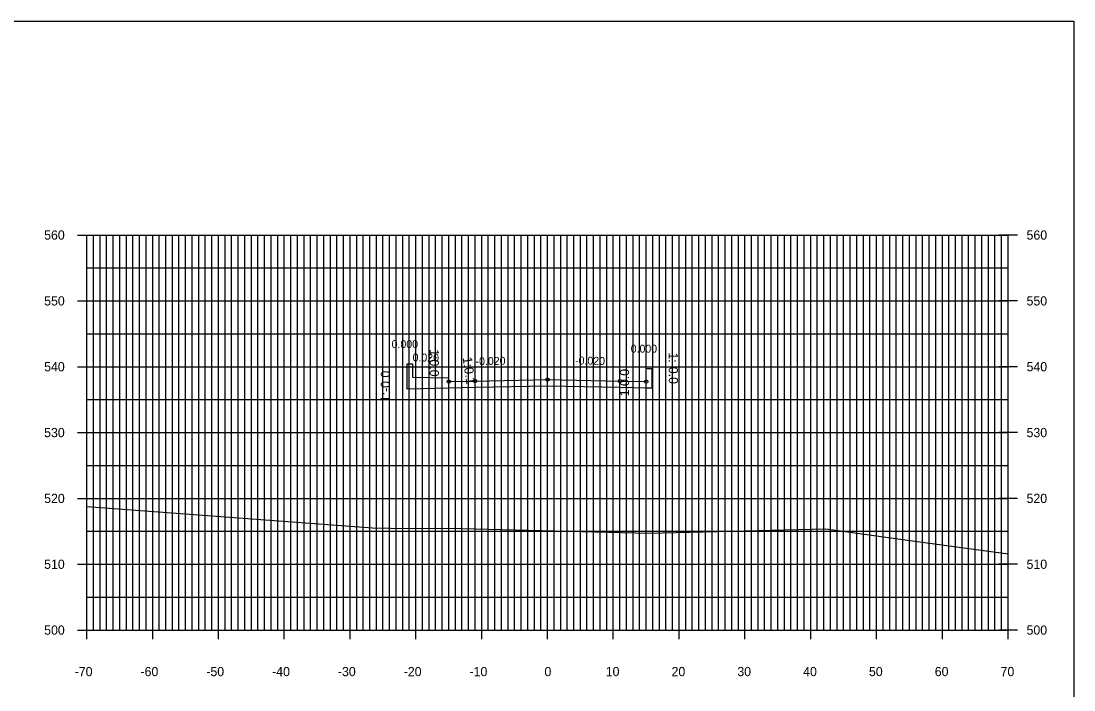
# Model space of a CAD drawing. Extents: x 1509063 to 1512863, y 401160 to 402918.
# Drawn here: x 1511262.7 to 1511422.7, y 402360.5 to 402462.1 of the extents above; entities that cross this region are included whole.
import ezdxf

# ---------------------------------------------------------------- set-up
doc = ezdxf.new("R2010")
doc.units = 0
for name, color, linetype in [('NBL1', 7, 'Continuous'), ('PET_P', 7, 'Continuous'), ('PRC', 7, 'Continuous'), ('PSP_P', 7, 'Continuous'), ('XAX_P', 7, 'Continuous'), ('XAXTIC_P', 7, 'Continuous'), ('XAXTXT_P_T', 7, 'Continuous'), ('XGL_P', 7, 'Continuous'), ('XSL1_P', 7, 'Continuous'), ('XSL1_P_T', 7, 'Continuous'), ('XSL3_P', 7, 'Continuous'), ('XSLOG', 7, 'Continuous')]:
    doc.layers.add(name, color=color, linetype=linetype)

msp = doc.modelspace()

# ---------------------------------------------------------------- linework, layer by layer
at = {"layer": 'NBL1'}
msp.add_lwpolyline([(1511422.73, 402252.08), (1511102.73, 402252.08), (1511102.73, 402462.08), (1511422.73, 402462.08)], close=True, dxfattribs=at)
at = {"layer": 'PET_P'}
for centre in [(1511331.73, 402407.4), (1511353.73, 402407.4)]:
    msp.add_circle(centre, 0.25, dxfattribs=at)
at = {"layer": 'PRC'}
msp.add_circle((1511342.73, 402407.62), 0.25, dxfattribs=at)
at = {"layer": 'PSP_P'}
for centre in [(1511327.73, 402407.32), (1511357.73, 402407.32)]:
    msp.add_circle(centre, 0.25, dxfattribs=at)
at = {"layer": 'XAX_P'}
for p, q in [((1511272.73, 402369.58), (1511272.73, 402429.58)), ((1511342.73, 402369.58), (1511342.73, 402429.58)), ((1511412.73, 402369.58), (1511412.73, 402429.58)), ((1511272.73, 402369.58), (1511412.73, 402369.58))]:
    msp.add_line(p, q, dxfattribs=at)
at = {"layer": 'XAXTIC_P'}
for p, q in [((1511271.33, 402429.58), (1511274.13, 402429.58)), ((1511341.33, 402429.58), (1511344.13, 402429.58)), ((1511414.13, 402429.58), (1511411.33, 402429.58)), ((1511271.33, 402419.58), (1511274.13, 402419.58)), ((1511341.33, 402419.58), (1511344.13, 402419.58)), ((1511414.13, 402419.58), (1511411.33, 402419.58)), ((1511271.33, 402409.58), (1511274.13, 402409.58)), ((1511341.33, 402409.58), (1511344.13, 402409.58)), ((1511414.13, 402409.58), (1511411.33, 402409.58)), ((1511271.33, 402399.58), (1511274.13, 402399.58)), ((1511341.33, 402399.58), (1511344.13, 402399.58)), ((1511414.13, 402399.58), (1511411.33, 402399.58)), ((1511271.33, 402389.58), (1511274.13, 402389.58)), ((1511341.33, 402389.58), (1511344.13, 402389.58)), ((1511414.13, 402389.58), (1511411.33, 402389.58)), ((1511271.33, 402379.58), (1511274.13, 402379.58)), ((1511341.33, 402379.58), (1511344.13, 402379.58)), ((1511414.13, 402379.58), (1511411.33, 402379.58)), ((1511272.73, 402368.18), (1511272.73, 402370.98)), ((1511282.73, 402368.18), (1511282.73, 402370.98)), ((1511292.73, 402368.18), (1511292.73, 402370.98)), ((1511302.73, 402368.18), (1511302.73, 402370.98)), ((1511312.73, 402368.18), (1511312.73, 402370.98)), ((1511322.73, 402368.18), (1511322.73, 402370.98)), ((1511332.73, 402368.18), (1511332.73, 402370.98)), ((1511342.73, 402368.18), (1511342.73, 402370.98)), ((1511352.73, 402368.18), (1511352.73, 402370.98)), ((1511362.73, 402368.18), (1511362.73, 402370.98)), ((1511372.73, 402368.18), (1511372.73, 402370.98)), ((1511382.73, 402368.18), (1511382.73, 402370.98)), ((1511392.73, 402368.18), (1511392.73, 402370.98)), ((1511402.73, 402368.18), (1511402.73, 402370.98)), ((1511412.73, 402368.18), (1511412.73, 402370.98)), ((1511271.33, 402369.58), (1511274.13, 402369.58)), ((1511341.33, 402369.58), (1511344.13, 402369.58)), ((1511414.13, 402369.58), (1511411.33, 402369.58))]:
    msp.add_line(p, q, dxfattribs=at)
at = {"layer": 'XGL_P'}
for p, q in [((1511272.73, 402429.58), (1511412.73, 402429.58)), ((1511272.73, 402369.58), (1511272.73, 402429.58)), ((1511273.73, 402369.58), (1511273.73, 402429.58)), ((1511274.73, 402369.58), (1511274.73, 402429.58)), ((1511275.73, 402369.58), (1511275.73, 402429.58)), ((1511276.73, 402369.58), (1511276.73, 402429.58)), ((1511277.73, 402369.58), (1511277.73, 402429.58)), ((1511278.73, 402369.58), (1511278.73, 402429.58)), ((1511279.73, 402369.58), (1511279.73, 402429.58)), ((1511280.73, 402369.58), (1511280.73, 402429.58)), ((1511281.73, 402369.58), (1511281.73, 402429.58)), ((1511282.73, 402369.58), (1511282.73, 402429.58)), ((1511283.73, 402369.58), (1511283.73, 402429.58)), ((1511284.73, 402369.58), (1511284.73, 402429.58)), ((1511285.73, 402369.58), (1511285.73, 402429.58)), ((1511286.73, 402369.58), (1511286.73, 402429.58)), ((1511287.73, 402369.58), (1511287.73, 402429.58)), ((1511288.73, 402369.58), (1511288.73, 402429.58)), ((1511289.73, 402369.58), (1511289.73, 402429.58)), ((1511290.73, 402369.58), (1511290.73, 402429.58)), ((1511291.73, 402369.58), (1511291.73, 402429.58)), ((1511292.73, 402369.58), (1511292.73, 402429.58)), ((1511293.73, 402369.58), (1511293.73, 402429.58)), ((1511294.73, 402369.58), (1511294.73, 402429.58)), ((1511295.73, 402369.58), (1511295.73, 402429.58)), ((1511296.73, 402369.58), (1511296.73, 402429.58)), ((1511297.73, 402369.58), (1511297.73, 402429.58)), ((1511298.73, 402369.58), (1511298.73, 402429.58)), ((1511299.73, 402369.58), (1511299.73, 402429.58)), ((1511300.73, 402369.58), (1511300.73, 402429.58)), ((1511301.73, 402369.58), (1511301.73, 402429.58)), ((1511302.73, 402369.58), (1511302.73, 402429.58)), ((1511303.73, 402369.58), (1511303.73, 402429.58)), ((1511304.73, 402369.58), (1511304.73, 402429.58)), ((1511305.73, 402369.58), (1511305.73, 402429.58)), ((1511306.73, 402369.58), (1511306.73, 402429.58)), ((1511307.73, 402369.58), (1511307.73, 402429.58)), ((1511308.73, 402369.58), (1511308.73, 402429.58)), ((1511309.73, 402369.58), (1511309.73, 402429.58)), ((1511310.73, 402369.58), (1511310.73, 402429.58)), ((1511311.73, 402369.58), (1511311.73, 402429.58)), ((1511312.73, 402369.58), (1511312.73, 402429.58)), ((1511313.73, 402369.58), (1511313.73, 402429.58)), ((1511314.73, 402369.58), (1511314.73, 402429.58)), ((1511315.73, 402369.58), (1511315.73, 402429.58)), ((1511316.73, 402369.58), (1511316.73, 402429.58)), ((1511317.73, 402369.58), (1511317.73, 402429.58)), ((1511318.73, 402369.58), (1511318.73, 402429.58)), ((1511319.73, 402369.58), (1511319.73, 402429.58)), ((1511320.73, 402369.58), (1511320.73, 402429.58)), ((1511321.73, 402369.58), (1511321.73, 402429.58)), ((1511322.73, 402369.58), (1511322.73, 402429.58)), ((1511323.73, 402369.58), (1511323.73, 402429.58)), ((1511324.73, 402369.58), (1511324.73, 402429.58)), ((1511325.73, 402369.58), (1511325.73, 402429.58)), ((1511326.73, 402369.58), (1511326.73, 402429.58)), ((1511327.73, 402369.58), (1511327.73, 402429.58)), ((1511328.73, 402369.58), (1511328.73, 402429.58)), ((1511329.73, 402369.58), (1511329.73, 402429.58)), ((1511330.73, 402369.58), (1511330.73, 402429.58)), ((1511331.73, 402369.58), (1511331.73, 402429.58)), ((1511332.73, 402369.58), (1511332.73, 402429.58)), ((1511333.73, 402369.58), (1511333.73, 402429.58)), ((1511334.73, 402369.58), (1511334.73, 402429.58)), ((1511335.73, 402369.58), (1511335.73, 402429.58)), ((1511336.73, 402369.58), (1511336.73, 402429.58)), ((1511337.73, 402369.58), (1511337.73, 402429.58)), ((1511338.73, 402369.58), (1511338.73, 402429.58)), ((1511339.73, 402369.58), (1511339.73, 402429.58)), ((1511340.73, 402369.58), (1511340.73, 402429.58)), ((1511341.73, 402369.58), (1511341.73, 402429.58)), ((1511342.73, 402369.58), (1511342.73, 402429.58)), ((1511343.73, 402369.58), (1511343.73, 402429.58)), ((1511344.73, 402369.58), (1511344.73, 402429.58)), ((1511345.73, 402369.58), (1511345.73, 402429.58)), ((1511346.73, 402369.58), (1511346.73, 402429.58)), ((1511347.73, 402369.58), (1511347.73, 402429.58)), ((1511348.73, 402369.58), (1511348.73, 402429.58)), ((1511349.73, 402369.58), (1511349.73, 402429.58)), ((1511350.73, 402369.58), (1511350.73, 402429.58)), ((1511351.73, 402369.58), (1511351.73, 402429.58)), ((1511352.73, 402369.58), (1511352.73, 402429.58)), ((1511353.73, 402369.58), (1511353.73, 402429.58)), ((1511354.73, 402369.58), (1511354.73, 402429.58)), ((1511355.73, 402369.58), (1511355.73, 402429.58)), ((1511356.73, 402369.58), (1511356.73, 402429.58)), ((1511357.73, 402369.58), (1511357.73, 402429.58)), ((1511358.73, 402369.58), (1511358.73, 402429.58)), ((1511359.73, 402369.58), (1511359.73, 402429.58)), ((1511360.73, 402369.58), (1511360.73, 402429.58)), ((1511361.73, 402369.58), (1511361.73, 402429.58)), ((1511362.73, 402369.58), (1511362.73, 402429.58)), ((1511363.73, 402369.58), (1511363.73, 402429.58)), ((1511364.73, 402369.58), (1511364.73, 402429.58)), ((1511365.73, 402369.58), (1511365.73, 402429.58)), ((1511366.73, 402369.58), (1511366.73, 402429.58)), ((1511367.73, 402369.58), (1511367.73, 402429.58)), ((1511368.73, 402369.58), (1511368.73, 402429.58)), ((1511369.73, 402369.58), (1511369.73, 402429.58)), ((1511370.73, 402369.58), (1511370.73, 402429.58)), ((1511371.73, 402369.58), (1511371.73, 402429.58)), ((1511372.73, 402369.58), (1511372.73, 402429.58)), ((1511373.73, 402369.58), (1511373.73, 402429.58)), ((1511374.73, 402369.58), (1511374.73, 402429.58)), ((1511375.73, 402369.58), (1511375.73, 402429.58)), ((1511376.73, 402369.58), (1511376.73, 402429.58)), ((1511377.73, 402369.58), (1511377.73, 402429.58)), ((1511378.73, 402369.58), (1511378.73, 402429.58)), ((1511379.73, 402369.58), (1511379.73, 402429.58)), ((1511380.73, 402369.58), (1511380.73, 402429.58)), ((1511381.73, 402369.58), (1511381.73, 402429.58)), ((1511382.73, 402369.58), (1511382.73, 402429.58)), ((1511383.73, 402369.58), (1511383.73, 402429.58)), ((1511384.73, 402369.58), (1511384.73, 402429.58)), ((1511385.73, 402369.58), (1511385.73, 402429.58)), ((1511386.73, 402369.58), (1511386.73, 402429.58)), ((1511387.73, 402369.58), (1511387.73, 402429.58)), ((1511388.73, 402369.58), (1511388.73, 402429.58)), ((1511389.73, 402369.58), (1511389.73, 402429.58)), ((1511390.73, 402369.58), (1511390.73, 402429.58)), ((1511391.73, 402369.58), (1511391.73, 402429.58)), ((1511392.73, 402369.58), (1511392.73, 402429.58)), ((1511393.73, 402369.58), (1511393.73, 402429.58)), ((1511394.73, 402369.58), (1511394.73, 402429.58)), ((1511395.73, 402369.58), (1511395.73, 402429.58)), ((1511396.73, 402369.58), (1511396.73, 402429.58)), ((1511397.73, 402369.58), (1511397.73, 402429.58)), ((1511398.73, 402369.58), (1511398.73, 402429.58)), ((1511399.73, 402369.58), (1511399.73, 402429.58)), ((1511400.73, 402369.58), (1511400.73, 402429.58)), ((1511401.73, 402369.58), (1511401.73, 402429.58)), ((1511402.73, 402369.58), (1511402.73, 402429.58)), ((1511403.73, 402369.58), (1511403.73, 402429.58)), ((1511404.73, 402369.58), (1511404.73, 402429.58)), ((1511405.73, 402369.58), (1511405.73, 402429.58)), ((1511406.73, 402369.58), (1511406.73, 402429.58)), ((1511407.73, 402369.58), (1511407.73, 402429.58)), ((1511408.73, 402369.58), (1511408.73, 402429.58)), ((1511409.73, 402369.58), (1511409.73, 402429.58)), ((1511410.73, 402369.58), (1511410.73, 402429.58)), ((1511411.73, 402369.58), (1511411.73, 402429.58)), ((1511412.73, 402369.58), (1511412.73, 402429.58)), ((1511272.73, 402424.58), (1511412.73, 402424.58)), ((1511272.73, 402419.58), (1511412.73, 402419.58)), ((1511272.73, 402414.58), (1511412.73, 402414.58)), ((1511272.73, 402409.58), (1511412.73, 402409.58)), ((1511272.73, 402404.58), (1511412.73, 402404.58)), ((1511272.73, 402399.58), (1511412.73, 402399.58)), ((1511272.73, 402394.58), (1511412.73, 402394.58)), ((1511272.73, 402389.58), (1511412.73, 402389.58)), ((1511272.73, 402384.58), (1511412.73, 402384.58)), ((1511272.73, 402379.58), (1511412.73, 402379.58)), ((1511272.73, 402374.58), (1511412.73, 402374.58)), ((1511272.73, 402369.58), (1511412.73, 402369.58))]:
    msp.add_line(p, q, dxfattribs=at)
at = {"layer": 'XSL1_P'}
msp.add_lwpolyline([(1511321.39, 402406.19), (1511321.4, 402410.01), (1511322.23, 402410.01), (1511322.23, 402408.01), (1511327.65, 402407.9), (1511327.73, 402407.32), (1511331.73, 402407.4), (1511342.73, 402407.62), (1511353.73, 402407.4), (1511357.73, 402407.32), (1511357.73, 402409.32), (1511358.56, 402409.32), (1511358.57, 402406.3)], dxfattribs=at)
at = {"layer": 'XSL3_P'}
msp.add_lwpolyline([(1511331.73, 402406.4), (1511327.73, 402406.32), (1511321.39, 402406.19), (1511321.4, 402410.01), (1511322.23, 402410.01), (1511322.23, 402408.01), (1511327.65, 402407.9), (1511327.73, 402407.32), (1511331.73, 402407.4), (1511342.72, 402407.62), (1511353.73, 402407.4), (1511357.73, 402407.32), (1511357.73, 402409.32), (1511358.56, 402409.32), (1511358.57, 402406.3), (1511357.73, 402406.32), (1511353.73, 402406.4), (1511342.72, 402406.62)], close=True, dxfattribs=at)
at = {"layer": 'XSLOG'}
msp.add_lwpolyline([(1511272.73, 402388.36), (1511316.14, 402385.09), (1511321.73, 402385.03), (1511327.62, 402385.08), (1511358.11, 402384.3), (1511385.05, 402384.97), (1511398.56, 402383.11), (1511412.73, 402381.16)], dxfattribs=at)

# ---------------------------------------------------------------- texts
at = {"layer": 'XAXTXT_P_T'}
for s, p in [('560', (1511266.24, 402428.88)), ('560', (1511415.53, 402428.88)), ('550', (1511266.24, 402418.88)), ('550', (1511415.53, 402418.88)), ('540', (1511266.24, 402408.88)), ('540', (1511415.53, 402408.88)), ('530', (1511266.24, 402398.88)), ('530', (1511415.53, 402398.88)), ('520', (1511266.24, 402388.88)), ('520', (1511415.53, 402388.88)), ('510', (1511266.24, 402378.88)), ('510', (1511415.53, 402378.88)), ('500', (1511266.24, 402368.88)), ('500', (1511415.53, 402368.88)), ('-70', (1511270.88, 402362.58)), ('-60', (1511280.88, 402362.58)), ('-50', (1511290.88, 402362.58)), ('-40', (1511300.88, 402362.58)), ('-30', (1511310.88, 402362.58)), ('-20', (1511320.88, 402362.58)), ('-10', (1511330.88, 402362.58)), ('0', (1511342.27, 402362.58)), ('10', (1511351.58, 402362.58)), ('20', (1511361.58, 402362.58)), ('30', (1511371.58, 402362.58)), ('40', (1511381.58, 402362.58)), ('50', (1511391.58, 402362.58)), ('60', (1511401.58, 402362.58)), ('70', (1511411.58, 402362.58))]:
    msp.add_text(s, height=1.4, dxfattribs=at).set_placement(p)
at = {"layer": 'XSL1_P_T'}
for s, height, rotation, p in [('0.000', 1.2, 360, (1511319.04, 402412.41)), ('0.000', 1.2, 360, (1511319.04, 402412.41)), ('0.000', 1.2, 360, (1511355.37, 402411.72)), ('0.000', 1.2, 360, (1511355.37, 402411.72)), ('0.020', 1.2, 358.8542, (1511322.21, 402410.41)), ('0.020', 1.2, 358.8542, (1511322.21, 402410.41)), ('1:0.0', 1.4, 270.0286, (1511324.83, 402412.25)), ('1:0.0', 1.4, 270.0286, (1511324.83, 402412.25)), ('1:-0.0', 1.4, 270.1899, (1511361.15, 402411.75)), ('1:-0.0', 1.4, 270.1899, (1511361.15, 402411.75)), ('1:0.1', 1.4, 278.1301, (1511329.83, 402410.96)), ('1:0.1', 1.4, 278.1301, (1511329.83, 402410.96)), ('-0.020', 1.2, 1.1458, (1511331.81, 402409.8)), ('-0.020', 1.2, 1.1458, (1511331.81, 402409.8)), ('-0.020', 1.2, 1.1458, (1511331.81, 402409.8)), ('-0.020', 1.2, 358.8542, (1511346.91, 402409.94)), ('-0.020', 1.2, 358.8542, (1511346.91, 402409.94)), ('-0.020', 1.2, 358.8542, (1511346.91, 402409.94)), ('1:-0.0', 1.4, 89.85, (1511318.78, 402404.18)), ('1:-0.0', 1.4, 89.85, (1511318.78, 402404.18)), ('1:0.0', 1.4, 89.9714, (1511355.13, 402405.08)), ('1:0.0', 1.4, 89.9714, (1511355.13, 402405.08))]:
    msp.add_text(s, height=height, rotation=rotation, dxfattribs=at).set_placement(p)

doc.saveas('drawing.dxf')
